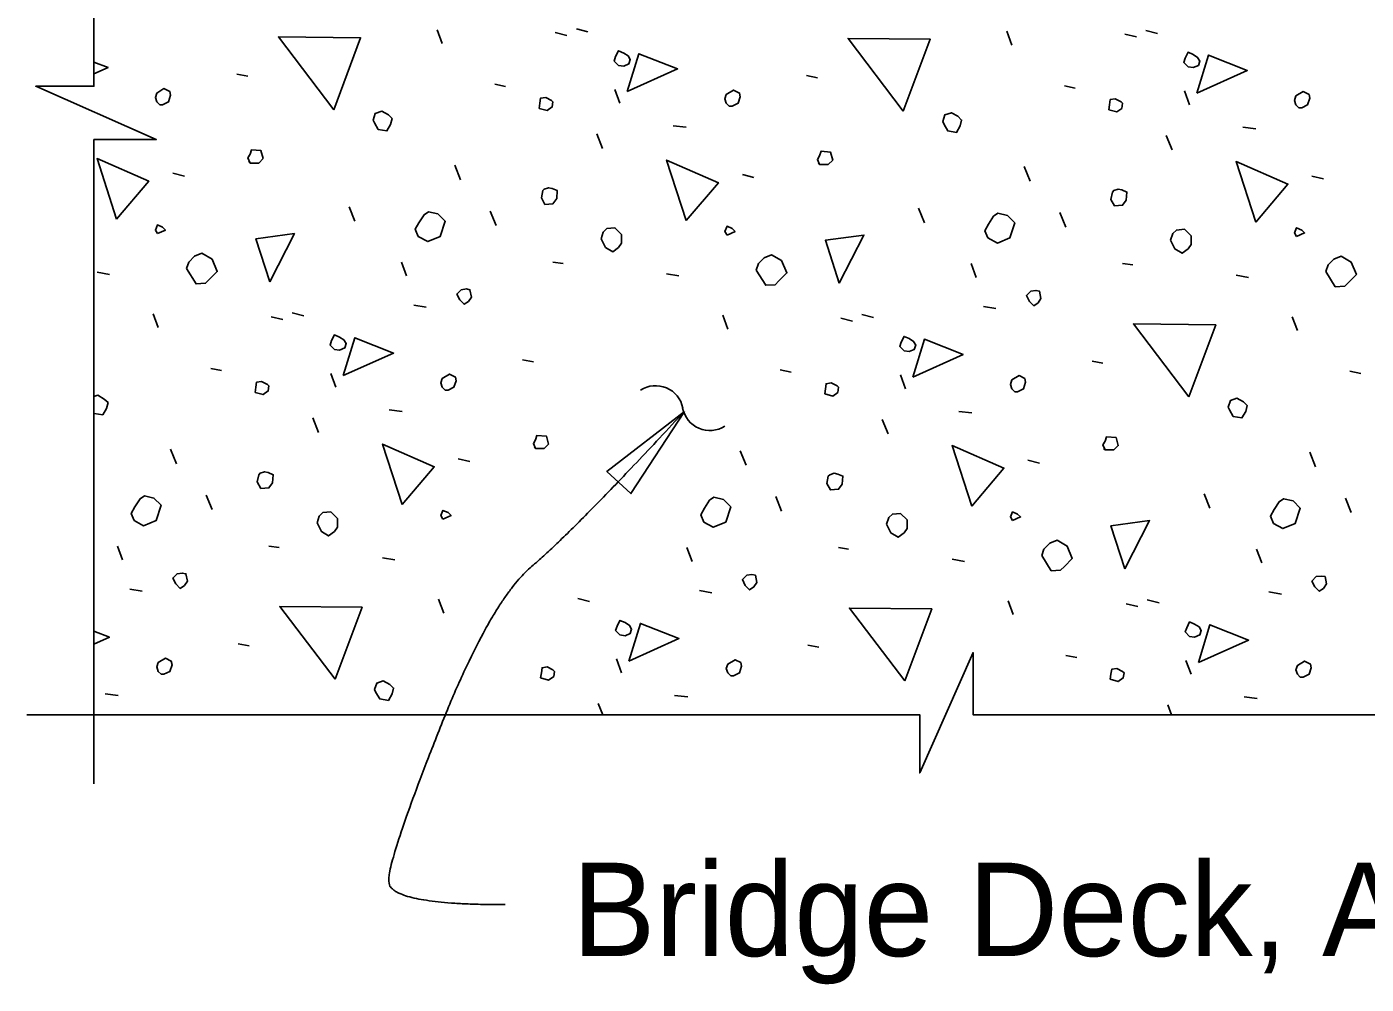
# Model space of a CAD drawing. Extents: x 0 to 15.4, y 0 to 9.7.
# Drawn here: x 1.982 to 3.065, y 1.753 to 2.528 of the extents above; entities that cross this region are included whole.
import ezdxf

# ---------------------------------------------------------------- set-up
doc = ezdxf.new("R2010")
doc.units = 0
doc.layers.add('Dimension', color=7, linetype='Continuous')
doc.layers.add('Miscellaneous', color=7, linetype='Continuous')

msp = doc.modelspace()

# ---------------------------------------------------------------- linework, layer by layer
at = {"layer": 'Dimension'}
for points in [[(2.0359, 1.9154), (2.0359, 2.4366), (2.0863, 2.4366), (1.9888, 2.4797), (2.0359, 2.4797), (2.0359, 2.9891)], [(3.2197, 1.9713), (2.7471, 1.9713), (2.7471, 2.0215), (2.704, 1.9242), (2.704, 1.9713), (1.9816, 1.9713)]]:
    msp.add_lwpolyline(points, dxfattribs=at)
msp.add_lwpolyline([(2.5136, 2.2166), (2.4509, 2.1681), (2.4704, 2.1502)], close=True, dxfattribs=at)
for centre, start, end in [((2.4903, 2.2151), 10.958, 122.6852), ((2.5342, 2.2236), 190.958, 302.6852)]:
    msp.add_arc(centre, 0.0224, start, end, dxfattribs=at)
msp.add_open_spline([(2.3686, 1.8176), (2.2743, 1.8176), (2.2743, 1.8554), (2.3564, 2.0627), (2.4234, 2.1194), (2.5136, 2.2166)], degree=2, dxfattribs=at)
at = {"layer": 'Miscellaneous'}
for p, q in [((2.3177, 2.5143), (2.3136, 2.5255)), ((2.4262, 2.5261), (2.4356, 2.5237)), ((2.887, 2.5249), (2.8964, 2.5225)), ((2.4091, 2.5231), (2.4185, 2.5208)), ((2.7785, 2.5131), (2.7744, 2.5243)), ((2.8699, 2.5219), (2.8793, 2.5196)), ((2.1516, 2.4895), (2.1604, 2.4878)), ((2.6124, 2.4884), (2.6212, 2.4866)), ((2.3602, 2.4813), (2.369, 2.4795)), ((2.4615, 2.466), (2.4574, 2.4772)), ((2.821, 2.4801), (2.8298, 2.4783)), ((2.9223, 2.4648), (2.9182, 2.476)), ((2.4474, 2.4294), (2.4427, 2.4412)), ((2.5045, 2.4477), (2.5151, 2.4465)), ((2.9082, 2.4283), (2.9035, 2.44)), ((2.9653, 2.4465), (2.9759, 2.4453)), ((2.0997, 2.4094), (2.1091, 2.407)), ((2.3325, 2.4041), (2.3278, 2.4159)), ((2.5605, 2.4082), (2.5699, 2.4059)), ((2.7933, 2.4029), (2.7886, 2.4147)), ((3.0213, 2.407), (3.0307, 2.4047)), ((2.247, 2.3705), (2.2423, 2.3823)), ((2.3613, 2.367), (2.3566, 2.3788)), ((2.7078, 2.3693), (2.7031, 2.3811)), ((2.8221, 2.3658), (2.8174, 2.3776)), ((2.2889, 2.3263), (2.2847, 2.3375)), ((2.4073, 2.3375), (2.4156, 2.3363)), ((2.7497, 2.3251), (2.7455, 2.3363)), ((2.8681, 2.3363), (2.8764, 2.3352)), ((2.0384, 2.3293), (2.0484, 2.3275)), ((2.4992, 2.3281), (2.5092, 2.3263)), ((2.96, 2.3269), (2.97, 2.3251)), ((2.2948, 2.3027), (2.3048, 2.301)), ((2.7556, 2.3016), (2.7656, 2.2998)), ((2.0879, 2.2845), (2.0838, 2.2957)), ((2.1793, 2.2933), (2.1887, 2.291)), ((2.1964, 2.2963), (2.2058, 2.2939)), ((2.5487, 2.2833), (2.5446, 2.2945)), ((2.6401, 2.2921), (2.6495, 2.2898)), ((2.6571, 2.2951), (2.6666, 2.2927)), ((3.0095, 2.2821), (3.0054, 2.2933)), ((2.3826, 2.2585), (2.3914, 2.2568)), ((2.8434, 2.2574), (2.8522, 2.2556)), ((2.1304, 2.2515), (2.1392, 2.2497)), ((2.2317, 2.2362), (2.2276, 2.2474)), ((2.5912, 2.2503), (2.6, 2.2485)), ((2.6925, 2.235), (2.6884, 2.2462)), ((3.052, 2.2491), (3.0608, 2.2474)), ((2.2176, 2.1996), (2.2129, 2.2114)), ((2.2747, 2.2179), (2.2853, 2.2167)), ((2.7355, 2.2167), (2.7461, 2.2155)), ((2.6784, 2.1984), (2.6736, 2.2102)), ((2.1027, 2.1743), (2.0979, 2.1861)), ((2.3307, 2.1784), (2.3401, 2.1761)), ((2.5635, 2.1731), (2.5587, 2.1849)), ((3.0243, 2.1719), (3.0195, 2.1837)), ((2.7915, 2.1772), (2.8009, 2.1749)), ((2.1315, 2.1372), (2.1268, 2.1489)), ((2.5923, 2.136), (2.5876, 2.1478)), ((2.9388, 2.1383), (2.9341, 2.1501)), ((3.0531, 2.1348), (3.0484, 2.1466)), ((2.0591, 2.0965), (2.0549, 2.1077)), ((2.1775, 2.1077), (2.1857, 2.1065)), ((2.5199, 2.0953), (2.5157, 2.1065)), ((2.6383, 2.1065), (2.6465, 2.1053)), ((2.9807, 2.0941), (2.9765, 2.1053)), ((2.2694, 2.0983), (2.2794, 2.0965)), ((2.7302, 2.0971), (2.7402, 2.0953)), ((2.0649, 2.0729), (2.075, 2.0712)), ((2.5257, 2.0718), (2.5358, 2.07)), ((2.9865, 2.0706), (2.9966, 2.0688)), ((2.3189, 2.0535), (2.3148, 2.0647)), ((2.4273, 2.0653), (2.4368, 2.0629)), ((2.7797, 2.0523), (2.7756, 2.0635)), ((2.871, 2.0611), (2.8805, 2.0588)), ((2.8881, 2.0641), (2.8976, 2.0617)), ((2.1527, 2.0287), (2.1616, 2.027)), ((2.6135, 2.0276), (2.6224, 2.0258)), ((2.4627, 2.0052), (2.4586, 2.0164)), ((2.8221, 2.0193), (2.831, 2.0175)), ((2.9235, 2.004), (2.9194, 2.0152)), ((2.0449, 1.9881), (2.0555, 1.9869)), ((2.5057, 1.9869), (2.5163, 1.9857)), ((2.9665, 1.9857), (2.9771, 1.9845)), ((2.4475, 1.9713), (2.4438, 1.9804)), ((2.9078, 1.9713), (2.9046, 1.9792))]:
    msp.add_line(p, q, dxfattribs=at)
for points in [[(2.2299, 2.4607), (2.1852, 2.5196), (2.2517, 2.519), (2.2299, 2.4607)], [(2.6907, 2.4595), (2.646, 2.5184), (2.7125, 2.5178), (2.6907, 2.4595)], [(2.4603, 2.4966), (2.4645, 2.496), (2.4686, 2.4978), (2.4698, 2.5013), (2.468, 2.5043), (2.4645, 2.5066), (2.4603, 2.5084), (2.458, 2.5037), (2.4568, 2.5001), (2.4603, 2.4966)], [(2.4674, 2.4754), (2.4768, 2.506), (2.5081, 2.4937), (2.4674, 2.4754)], [(2.9211, 2.4954), (2.9253, 2.4948), (2.9294, 2.4966), (2.9306, 2.5001), (2.9288, 2.5031), (2.9253, 2.5054), (2.9211, 2.5072), (2.9188, 2.5025), (2.9176, 2.499), (2.9211, 2.4954)], [(2.9282, 2.4742), (2.9376, 2.5049), (2.9689, 2.4925), (2.9282, 2.4742)], [(2.0359, 2.4993), (2.0473, 2.4948), (2.0359, 2.4897)], [(2.0891, 2.4648), (2.0915, 2.4648), (2.0962, 2.4671), (2.0979, 2.4724), (2.0974, 2.4754), (2.0926, 2.4778), (2.0867, 2.4742), (2.0856, 2.4707), (2.0867, 2.4671), (2.0891, 2.4648)], [(2.3961, 2.4618), (2.4026, 2.4601), (2.4067, 2.463), (2.4073, 2.4671), (2.4061, 2.4683), (2.4014, 2.4707), (2.3973, 2.4701), (2.3967, 2.466), (2.3961, 2.4618)], [(2.5499, 2.4636), (2.5523, 2.4636), (2.557, 2.466), (2.5587, 2.4713), (2.5582, 2.4742), (2.5534, 2.4766), (2.5475, 2.473), (2.5464, 2.4695), (2.5475, 2.466), (2.5499, 2.4636)], [(3.0107, 2.4624), (3.0131, 2.4624), (3.0178, 2.4648), (3.0195, 2.4701), (3.019, 2.473), (3.0142, 2.4754), (3.0083, 2.4719), (3.0072, 2.4683), (3.0083, 2.4648), (3.0107, 2.4624)], [(2.8569, 2.4607), (2.8634, 2.4589), (2.8675, 2.4618), (2.8681, 2.466), (2.8669, 2.4671), (2.8622, 2.4695), (2.8581, 2.4689), (2.8575, 2.4648), (2.8569, 2.4607)], [(2.2629, 2.4501), (2.2659, 2.4448), (2.273, 2.4436), (2.2759, 2.4489), (2.2771, 2.4536), (2.2741, 2.4565), (2.2688, 2.4595), (2.2635, 2.4577), (2.2618, 2.4524), (2.2629, 2.4501)], [(2.7237, 2.4489), (2.7267, 2.4436), (2.7338, 2.4424), (2.7367, 2.4477), (2.7379, 2.4524), (2.7349, 2.4554), (2.7296, 2.4583), (2.7243, 2.4565), (2.7226, 2.4512), (2.7237, 2.4489)], [(2.1622, 2.4176), (2.1692, 2.4176), (2.1728, 2.4212), (2.171, 2.4277), (2.1634, 2.4283), (2.1622, 2.4247), (2.1604, 2.4218), (2.1622, 2.4176), (2.161, 2.4188)], [(2.0543, 2.3723), (2.0384, 2.4212), (2.0803, 2.4029), (2.0543, 2.3723)], [(2.5151, 2.3711), (2.4992, 2.42), (2.5411, 2.4017), (2.5151, 2.3711)], [(2.623, 2.4165), (2.63, 2.4165), (2.6336, 2.42), (2.6318, 2.4265), (2.6242, 2.4271), (2.623, 2.4235), (2.6212, 2.4206), (2.623, 2.4165), (2.6218, 2.4176)], [(2.9759, 2.3699), (2.96, 2.4188), (3.0019, 2.4006), (2.9759, 2.3699)], [(2.3979, 2.3894), (2.4008, 2.3841), (2.4073, 2.3847), (2.4103, 2.3888), (2.4108, 2.3953), (2.4067, 2.397), (2.4038, 2.3976), (2.4002, 2.3964), (2.3991, 2.3953), (2.3979, 2.3894)], [(2.8587, 2.3882), (2.8616, 2.3829), (2.8681, 2.3835), (2.871, 2.3876), (2.8716, 2.3941), (2.8675, 2.3958), (2.8646, 2.3964), (2.861, 2.3953), (2.8599, 2.3941), (2.8587, 2.3882)], [(2.2983, 2.3581), (2.306, 2.354), (2.316, 2.3581), (2.3201, 2.3705), (2.3142, 2.3764), (2.3065, 2.3782), (2.303, 2.3758), (2.2989, 2.3693), (2.2959, 2.364), (2.2983, 2.3581)], [(2.7591, 2.357), (2.7668, 2.3528), (2.7768, 2.357), (2.7809, 2.3693), (2.775, 2.3752), (2.7673, 2.377), (2.7638, 2.3746), (2.7597, 2.3682), (2.7567, 2.3628), (2.7591, 2.357)], [(2.0873, 2.3605), (2.0938, 2.3634), (2.0915, 2.3658), (2.0873, 2.3676), (2.0856, 2.3634), (2.0873, 2.3605)], [(2.4462, 2.3564), (2.4497, 2.3493), (2.4556, 2.3458), (2.4603, 2.3493), (2.4627, 2.3528), (2.4627, 2.3599), (2.4574, 2.3652), (2.4509, 2.3646), (2.448, 2.3617), (2.4462, 2.3564)], [(2.5481, 2.3593), (2.5546, 2.3623), (2.5523, 2.3646), (2.5481, 2.3664), (2.5464, 2.3623), (2.5481, 2.3593)], [(2.907, 2.3552), (2.9105, 2.3481), (2.9164, 2.3446), (2.9211, 2.3481), (2.9235, 2.3517), (2.9235, 2.3587), (2.9182, 2.364), (2.9117, 2.3634), (2.9088, 2.3605), (2.907, 2.3552)], [(3.0089, 2.3581), (3.0154, 2.3611), (3.0131, 2.3634), (3.0089, 2.3652), (3.0072, 2.3611), (3.0089, 2.3581)], [(2.1781, 2.3216), (2.1669, 2.3564), (2.1981, 2.3605), (2.1781, 2.3216)], [(2.6389, 2.3204), (2.6277, 2.3552), (2.6589, 2.3593), (2.6389, 2.3204)], [(2.1109, 2.3322), (2.1186, 2.3198), (2.1262, 2.3204), (2.1292, 2.3234), (2.1357, 2.3298), (2.1315, 2.3399), (2.1233, 2.3446), (2.1174, 2.3422), (2.1127, 2.3375), (2.1109, 2.3322)], [(2.5717, 2.331), (2.5794, 2.3187), (2.587, 2.3192), (2.59, 2.3222), (2.5965, 2.3287), (2.5923, 2.3387), (2.5841, 2.3434), (2.5782, 2.341), (2.5735, 2.3363), (2.5717, 2.331)], [(3.0325, 2.3298), (3.0402, 2.3175), (3.0478, 2.3181), (3.0508, 2.321), (3.0573, 2.3275), (3.0531, 2.3375), (3.0449, 2.3422), (3.039, 2.3399), (3.0343, 2.3352), (3.0325, 2.3298)], [(2.3319, 2.3069), (2.3354, 2.3033), (2.339, 2.3057), (2.3413, 2.3092), (2.3401, 2.3151), (2.3372, 2.3157), (2.3331, 2.3151), (2.3295, 2.3116), (2.3319, 2.3069)], [(2.7927, 2.3057), (2.7962, 2.3022), (2.7997, 2.3045), (2.8021, 2.308), (2.8009, 2.3139), (2.798, 2.3145), (2.7939, 2.3139), (2.7903, 2.3104), (2.7927, 2.3057)], [(2.9217, 2.2285), (2.8769, 2.2874), (2.9435, 2.2868), (2.9217, 2.2285)], [(2.2305, 2.2668), (2.2347, 2.2662), (2.2388, 2.268), (2.24, 2.2715), (2.2382, 2.2745), (2.2347, 2.2768), (2.2305, 2.2786), (2.2282, 2.2739), (2.227, 2.2703), (2.2305, 2.2668)], [(2.2376, 2.2456), (2.247, 2.2762), (2.2783, 2.2639), (2.2376, 2.2456)], [(2.6913, 2.2656), (2.6955, 2.265), (2.6996, 2.2668), (2.7008, 2.2703), (2.699, 2.2733), (2.6955, 2.2756), (2.6913, 2.2774), (2.689, 2.2727), (2.6878, 2.2692), (2.6913, 2.2656)], [(2.6984, 2.2444), (2.7078, 2.275), (2.7391, 2.2627), (2.6984, 2.2444)], [(2.3201, 2.2338), (2.3225, 2.2338), (2.3272, 2.2362), (2.3289, 2.2415), (2.3283, 2.2444), (2.3236, 2.2468), (2.3177, 2.2432), (2.3166, 2.2397), (2.3177, 2.2362), (2.3201, 2.2338)], [(2.7809, 2.2326), (2.7832, 2.2326), (2.788, 2.235), (2.7897, 2.2403), (2.7891, 2.2432), (2.7844, 2.2456), (2.7785, 2.2421), (2.7774, 2.2385), (2.7785, 2.235), (2.7809, 2.2326)], [(2.1663, 2.232), (2.1728, 2.2303), (2.1769, 2.2332), (2.1775, 2.2373), (2.1763, 2.2385), (2.1716, 2.2409), (2.1675, 2.2403), (2.1669, 2.2362), (2.1663, 2.232)], [(2.6271, 2.2309), (2.6336, 2.2291), (2.6377, 2.232), (2.6383, 2.2362), (2.6371, 2.2373), (2.6324, 2.2397), (2.6283, 2.2391), (2.6277, 2.235), (2.6271, 2.2309)], [(2.0359, 2.2152), (2.0361, 2.2149), (2.0431, 2.2138), (2.0461, 2.2191), (2.0473, 2.2238), (2.0443, 2.2267), (2.039, 2.2297), (2.0359, 2.2286)], [(2.9547, 2.2179), (2.9577, 2.2126), (2.9647, 2.2114), (2.9677, 2.2167), (2.9689, 2.2214), (2.9659, 2.2244), (2.9606, 2.2273), (2.9553, 2.2256), (2.9535, 2.2202), (2.9547, 2.2179)], [(2.2853, 2.1413), (2.2694, 2.1902), (2.3113, 2.1719), (2.2853, 2.1413)], [(2.3932, 2.1867), (2.4002, 2.1867), (2.4038, 2.1902), (2.402, 2.1967), (2.3943, 2.1973), (2.3932, 2.1937), (2.3914, 2.1908), (2.3932, 2.1867), (2.392, 2.1878)], [(2.7461, 2.1401), (2.7302, 2.189), (2.7721, 2.1708), (2.7461, 2.1401)], [(2.854, 2.1855), (2.861, 2.1855), (2.8646, 2.189), (2.8628, 2.1955), (2.8551, 2.1961), (2.854, 2.1926), (2.8522, 2.1896), (2.854, 2.1855), (2.8528, 2.1867)], [(2.1681, 2.1596), (2.171, 2.1543), (2.1775, 2.1548), (2.1804, 2.159), (2.181, 2.1654), (2.1769, 2.1672), (2.174, 2.1678), (2.1704, 2.1666), (2.1692, 2.1654), (2.1681, 2.1596)], [(2.6289, 2.1584), (2.6318, 2.1531), (2.6383, 2.1537), (2.6412, 2.1578), (2.6418, 2.1643), (2.6377, 2.166), (2.6348, 2.1666), (2.6312, 2.1654), (2.63, 2.1643), (2.6289, 2.1584)], [(2.0685, 2.1283), (2.0761, 2.1242), (2.0862, 2.1283), (2.0903, 2.1407), (2.0844, 2.1466), (2.0767, 2.1484), (2.0732, 2.146), (2.0691, 2.1395), (2.0661, 2.1342), (2.0685, 2.1283)], [(2.5293, 2.1271), (2.5369, 2.123), (2.547, 2.1271), (2.5511, 2.1395), (2.5452, 2.1454), (2.5375, 2.1472), (2.534, 2.1448), (2.5299, 2.1383), (2.5269, 2.133), (2.5293, 2.1271)], [(2.9901, 2.126), (2.9977, 2.1218), (3.0078, 2.126), (3.0119, 2.1383), (3.006, 2.1442), (2.9983, 2.146), (2.9948, 2.1436), (2.9907, 2.1372), (2.9877, 2.1319), (2.9901, 2.126)], [(2.2164, 2.1266), (2.2199, 2.1195), (2.2258, 2.1159), (2.2305, 2.1195), (2.2329, 2.123), (2.2329, 2.1301), (2.2276, 2.1354), (2.2211, 2.1348), (2.2182, 2.1319), (2.2164, 2.1266)], [(2.3183, 2.1295), (2.3248, 2.1324), (2.3225, 2.1348), (2.3183, 2.1366), (2.3166, 2.1324), (2.3183, 2.1295)], [(2.7791, 2.1283), (2.7856, 2.1313), (2.7832, 2.1336), (2.7791, 2.1354), (2.7774, 2.1313), (2.7791, 2.1283)], [(2.6772, 2.1254), (2.6807, 2.1183), (2.6866, 2.1148), (2.6913, 2.1183), (2.6937, 2.1218), (2.6937, 2.1289), (2.6884, 2.1342), (2.6819, 2.1336), (2.679, 2.1307), (2.6772, 2.1254)], [(2.8699, 2.0894), (2.8587, 2.1242), (2.8899, 2.1283), (2.8699, 2.0894)], [(2.8027, 2.1), (2.8104, 2.0877), (2.818, 2.0883), (2.821, 2.0912), (2.8274, 2.0977), (2.8233, 2.1077), (2.8151, 2.1124), (2.8092, 2.1101), (2.8045, 2.1053), (2.8027, 2.1)], [(2.1021, 2.0771), (2.1056, 2.0735), (2.1091, 2.0759), (2.1115, 2.0794), (2.1103, 2.0853), (2.1074, 2.0859), (2.1032, 2.0853), (2.0997, 2.0818), (2.1021, 2.0771)], [(2.5629, 2.0759), (2.5664, 2.0723), (2.5699, 2.0747), (2.5723, 2.0782), (2.5711, 2.0841), (2.5682, 2.0847), (2.564, 2.0841), (2.5605, 2.0806), (2.5629, 2.0759)], [(3.0237, 2.0747), (3.0272, 2.0712), (3.0307, 2.0735), (3.0331, 2.0771), (3.0319, 2.083), (3.029, 2.0835), (3.0248, 2.083), (3.0213, 2.0794), (3.0237, 2.0747)], [(2.2311, 1.9999), (2.1863, 2.0588), (2.2529, 2.0582), (2.2311, 1.9999)], [(2.6919, 1.9987), (2.6471, 2.0576), (2.7137, 2.057), (2.6919, 1.9987)], [(2.0359, 2.039), (2.0484, 2.034), (2.0359, 2.0284)], [(2.4615, 2.0358), (2.4656, 2.0352), (2.4698, 2.037), (2.4709, 2.0405), (2.4692, 2.0435), (2.4656, 2.0458), (2.4615, 2.0476), (2.4592, 2.0429), (2.458, 2.0393), (2.4615, 2.0358)], [(2.4686, 2.0146), (2.478, 2.0452), (2.5092, 2.0329), (2.4686, 2.0146)], [(2.9223, 2.0346), (2.9264, 2.034), (2.9306, 2.0358), (2.9317, 2.0393), (2.93, 2.0423), (2.9264, 2.0446), (2.9223, 2.0464), (2.92, 2.0417), (2.9188, 2.0382), (2.9223, 2.0346)], [(2.9294, 2.0134), (2.9388, 2.0441), (2.97, 2.0317), (2.9294, 2.0134)], [(2.0903, 2.004), (2.0926, 2.004), (2.0974, 2.0063), (2.0991, 2.0117), (2.0985, 2.0146), (2.0938, 2.017), (2.0879, 2.0134), (2.0867, 2.0099), (2.0879, 2.0063), (2.0903, 2.004)], [(2.5511, 2.0028), (2.5534, 2.0028), (2.5582, 2.0052), (2.5599, 2.0105), (2.5593, 2.0134), (2.5546, 2.0158), (2.5487, 2.0122), (2.5475, 2.0087), (2.5487, 2.0052), (2.5511, 2.0028)], [(2.3973, 2.001), (2.4038, 1.9993), (2.4079, 2.0022), (2.4085, 2.0063), (2.4073, 2.0075), (2.4026, 2.0099), (2.3985, 2.0093), (2.3979, 2.0052), (2.3973, 2.001)], [(2.8581, 1.9999), (2.8646, 1.9981), (2.8687, 2.001), (2.8693, 2.0052), (2.8681, 2.0063), (2.8634, 2.0087), (2.8593, 2.0081), (2.8587, 2.004), (2.8581, 1.9999)], [(3.0119, 2.0016), (3.0142, 2.0016), (3.019, 2.004), (3.0207, 2.0093), (3.0201, 2.0122), (3.0154, 2.0146), (3.0095, 2.0111), (3.0083, 2.0075), (3.0095, 2.004), (3.0119, 2.0016)], [(2.2641, 1.9893), (2.2671, 1.984), (2.2741, 1.9828), (2.2771, 1.9881), (2.2783, 1.9928), (2.2753, 1.9957), (2.27, 1.9987), (2.2647, 1.9969), (2.2629, 1.9916), (2.2641, 1.9893)]]:
    msp.add_lwpolyline(points, dxfattribs=at)

# ---------------------------------------------------------------- texts
at = {"layer": 'Dimension'}
msp.add_text('Bridge Deck, Approach ', height=0.0756, dxfattribs=at).set_placement((2.4227, 1.776))

doc.saveas('drawing.dxf')
